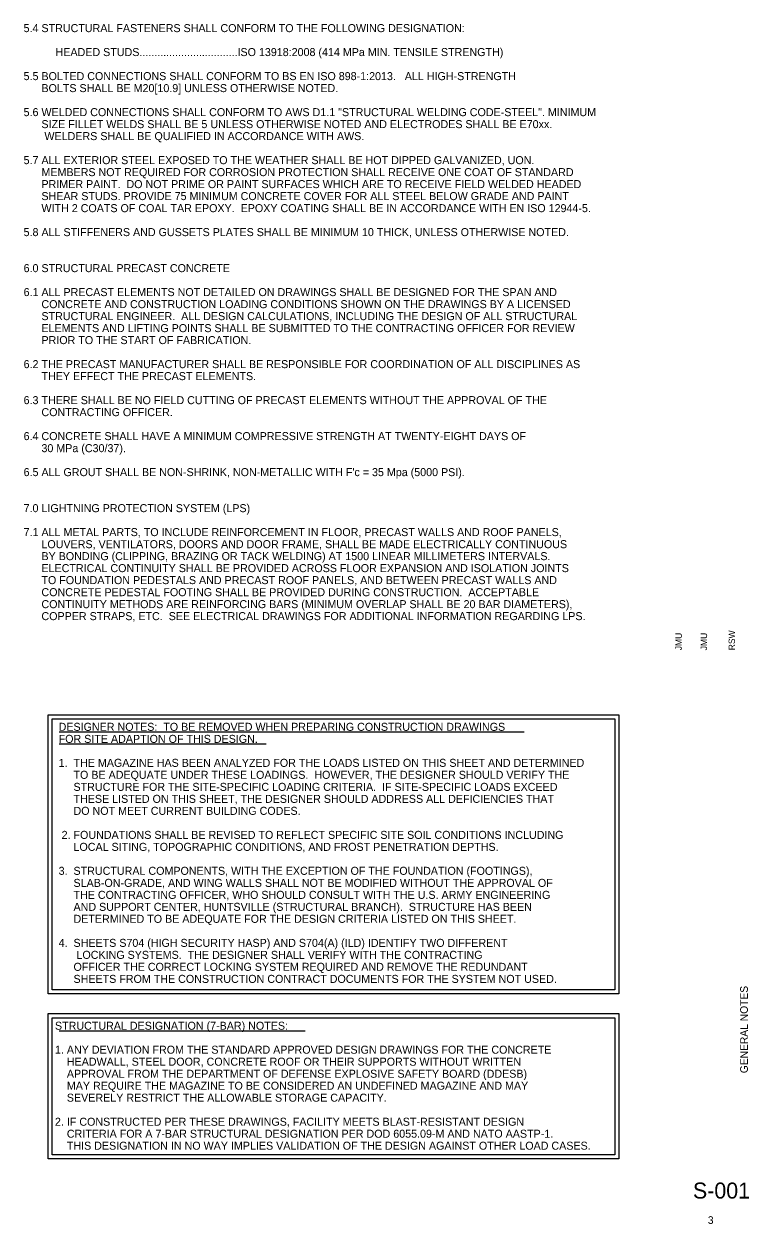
# Model space of a CAD drawing. Extents: x 0.17 to 2.69, y 0.11 to 1.7.
# Drawn here: x 1.747 to 2.69, y 0.138 to 1.7 of the extents above; entities that cross this region are included whole.
import ezdxf

# ---------------------------------------------------------------- set-up
doc = ezdxf.new("R2010")
doc.units = 0
doc.layers.add('G-ANNO-TEXT', color=7, linetype='Continuous')
doc.layers.add('G-ANNO-TTLB', color=7, linetype='Continuous')

msp = doc.modelspace()

# ---------------------------------------------------------------- linework, layer by layer
at = {"layer": 'G-ANNO-TEXT'}
for p, q in [((1.7925, 0.7787), (2.3978, 0.7787)), ((1.7925, 0.7631), (2.062, 0.7631)), ((1.7925, 0.3896), (2.1125, 0.3896))]:
    msp.add_line(p, q, dxfattribs=at)
for points in [[(1.7783, 0.8011), (2.5212, 0.8011), (2.5212, 0.4379), (1.7783, 0.4379)], [(1.7835, 0.7959), (2.516, 0.7959), (2.516, 0.4431), (1.7835, 0.4431)], [(1.7783, 0.412), (2.5212, 0.412), (2.5212, 0.2228), (1.7783, 0.2228)], [(1.7835, 0.4067), (2.516, 0.4067), (2.516, 0.228), (1.7835, 0.228)]]:
    msp.add_lwpolyline(points, close=True, dxfattribs=at)

# ---------------------------------------------------------------- texts
for s, p in [('5.4 STRUCTURAL FASTENERS SHALL CONFORM TO THE FOLLOWING DESIGNATION:', (1.7462, 1.6899)), ('HEADED STUDS.................................ISO 13918:2008 (414 MPa MIN. TENSILE STRENGTH)', (1.7878, 1.6587)), ('5.5 BOLTED CONNECTIONS SHALL CONFORM TO BS EN ISO 898-1:2013.   ALL HIGH-STRENGTH', (1.7462, 1.6274)), ('      BOLTS SHALL BE M20[10.9] UNLESS OTHERWISE NOTED.', (1.7462, 1.6118)), ('5.6 WELDED CONNECTIONS SHALL CONFORM TO AWS D1.1 "STRUCTURAL WELDING CODE-STEEL". MINIMUM', (1.7462, 1.5805)), ('      SIZE FILLET WELDS SHALL BE 5 UNLESS OTHERWISE NOTED AND ELECTRODES SHALL BE E70xx. ', (1.7462, 1.5649)), ('       WELDERS SHALL BE QUALIFIED IN ACCORDANCE WITH AWS.', (1.7462, 1.5493)), ('5.7 ALL EXTERIOR STEEL EXPOSED TO THE WEATHER SHALL BE HOT DIPPED GALVANIZED, UON. ', (1.7462, 1.518)), ('      MEMBERS NOT REQUIRED FOR CORROSION PROTECTION SHALL RECEIVE ONE COAT OF STANDARD ', (1.7462, 1.5024)), ('      PRIMER PAINT.  DO NOT PRIME OR PAINT SURFACES WHICH ARE TO RECEIVE FIELD WELDED HEADED ', (1.7462, 1.4868)), ('      SHEAR STUDS. PROVIDE 75 MINIMUM CONCRETE COVER FOR ALL STEEL BELOW GRADE AND PAINT ', (1.7462, 1.4712)), ('      WITH 2 COATS OF COAL TAR EPOXY.  EPOXY COATING SHALL BE IN ACCORDANCE WITH EN ISO 12944-5.   ', (1.7462, 1.4555)), ('5.8 ALL STIFFENERS AND GUSSETS PLATES SHALL BE MINIMUM 10 THICK, UNLESS OTHERWISE NOTED. ', (1.7462, 1.4243)), ('6.0 STRUCTURAL PRECAST CONCRETE', (1.7462, 1.3774)), ('6.1 ALL PRECAST ELEMENTS NOT DETAILED ON DRAWINGS SHALL BE DESIGNED FOR THE SPAN AND', (1.7462, 1.3462)), ('      CONCRETE AND CONSTRUCTION LOADING CONDITIONS SHOWN ON THE DRAWINGS BY A LICENSED', (1.7462, 1.3305)), ('      STRUCTURAL ENGINEER.  ALL DESIGN CALCULATIONS, INCLUDING THE DESIGN OF ALL STRUCTURAL', (1.7462, 1.3149)), ('      ELEMENTS AND LIFTING POINTS SHALL BE SUBMITTED TO THE CONTRACTING OFFICER FOR REVIEW', (1.7462, 1.2993)), ('      PRIOR TO THE START OF FABRICATION.', (1.7462, 1.2837)), ('6.2 THE PRECAST MANUFACTURER SHALL BE RESPONSIBLE FOR COORDINATION OF ALL DISCIPLINES AS', (1.7462, 1.2524)), ('      THEY EFFECT THE PRECAST ELEMENTS.', (1.7462, 1.2368)), ('6.3 THERE SHALL BE NO FIELD CUTTING OF PRECAST ELEMENTS WITHOUT THE APPROVAL OF THE', (1.7462, 1.2055)), ('      CONTRACTING OFFICER.', (1.7462, 1.1899)), ('6.4 CONCRETE SHALL HAVE A MINIMUM COMPRESSIVE STRENGTH AT TWENTY-EIGHT DAYS OF', (1.7462, 1.1587)), ('      30 MPa (C30/37).', (1.7462, 1.143)), ("6.5 ALL GROUT SHALL BE NON-SHRINK, NON-METALLIC WITH F'c = 35 Mpa (5000 PSI).", (1.7462, 1.1118)), ('7.0 LIGHTNING PROTECTION SYSTEM (LPS)', (1.7462, 1.0649)), ('7.1 ALL METAL PARTS, TO INCLUDE REINFORCEMENT IN FLOOR, PRECAST WALLS AND ROOF PANELS,', (1.7462, 1.0337)), ('      LOUVERS, VENTILATORS, DOORS AND DOOR FRAME, SHALL BE MADE ELECTRICALLY CONTINUOUS', (1.7462, 1.018)), ('      BY BONDING (CLIPPING, BRAZING OR TACK WELDING) AT 1500 LINEAR MILLIMETERS INTERVALS.  ', (1.7462, 1.0024)), ('      ELECTRICAL CONTINUITY SHALL BE PROVIDED ACROSS FLOOR EXPANSION AND ISOLATION JOINTS', (1.7462, 0.9868)), ('      TO FOUNDATION PEDESTALS AND PRECAST ROOF PANELS, AND BETWEEN PRECAST WALLS AND', (1.7462, 0.9712)), ('      CONCRETE PEDESTAL FOOTING SHALL BE PROVIDED DURING CONSTRUCTION.  ACCEPTABLE', (1.7462, 0.9555)), ('      CONTINUITY METHODS ARE REINFORCING BARS (MINIMUM OVERLAP SHALL BE 20 BAR DIAMETERS),', (1.7462, 0.9399)), ('      COPPER STRAPS, ETC.  SEE ELECTRICAL DRAWINGS FOR ADDITIONAL INFORMATION REGARDING LPS.', (1.7462, 0.9243)), ('DESIGNER NOTES:  TO BE REMOVED WHEN PREPARING CONSTRUCTION DRAWINGS ', (1.7918, 0.7802)), ('FOR SITE ADAPTION OF THIS DESIGN.', (1.7918, 0.7645)), ('1.  THE MAGAZINE HAS BEEN ANALYZED FOR THE LOADS LISTED ON THIS SHEET AND DETERMINED', (1.7918, 0.7333)), ('     TO BE ADEQUATE UNDER THESE LOADINGS.  HOWEVER, THE DESIGNER SHOULD VERIFY THE ', (1.7918, 0.7177)), ('     STRUCTURE FOR THE SITE-SPECIFIC LOADING CRITERIA.  IF SITE-SPECIFIC LOADS EXCEED ', (1.7918, 0.702)), ('     THESE LISTED ON THIS SHEET, THE DESIGNER SHOULD ADDRESS ALL DEFICIENCIES THAT', (1.7918, 0.6864)), ('     DO NOT MEET CURRENT BUILDING CODES. ', (1.7918, 0.6708)), (' 2. FOUNDATIONS SHALL BE REVISED TO REFLECT SPECIFIC SITE SOIL CONDITIONS INCLUDING', (1.7918, 0.6395)), ('     LOCAL SITING, TOPOGRAPHIC CONDITIONS, AND FROST PENETRATION DEPTHS.', (1.7918, 0.6239)), ('3.  STRUCTURAL COMPONENTS, WITH THE EXCEPTION OF THE FOUNDATION (FOOTINGS),', (1.7918, 0.5927)), ('     SLAB-ON-GRADE, AND WING WALLS SHALL NOT BE MODIFIED WITHOUT THE APPROVAL OF', (1.7918, 0.577)), ('     THE CONTRACTING OFFICER, WHO SHOULD CONSULT WITH THE U.S. ARMY ENGINEERING', (1.7918, 0.5614)), ('     AND SUPPORT CENTER, HUNTSVILLE (STRUCTURAL BRANCH).  STRUCTURE HAS BEEN', (1.7918, 0.5458)), ('     DETERMINED TO BE ADEQUATE FOR THE DESIGN CRITERIA LISTED ON THIS SHEET.    ', (1.7918, 0.5302)), ('4.  SHEETS S704 (HIGH SECURITY HASP) AND S704(A) (ILD) IDENTIFY TWO DIFFERENT', (1.7918, 0.4989)), ('      LOCKING SYSTEMS.  THE DESIGNER SHALL VERIFY WITH THE CONTRACTING', (1.7918, 0.4833)), ('     OFFICER THE CORRECT LOCKING SYSTEM REQUIRED AND REMOVE THE REDUNDANT', (1.7918, 0.4677)), ('     SHEETS FROM THE CONSTRUCTION CONTRACT DOCUMENTS FOR THE SYSTEM NOT USED.', (1.7918, 0.452)), ('STRUCTURAL DESIGNATION (7-BAR) NOTES:', (1.787, 0.391)), ('1. ANY DEVIATION FROM THE STANDARD APPROVED DESIGN DRAWINGS FOR THE CONCRETE', (1.787, 0.3598)), ('    HEADWALL, STEEL DOOR, CONCRETE ROOF OR THEIR SUPPORTS WITHOUT WRITTEN ', (1.787, 0.3442)), ('    APPROVAL FROM THE DEPARTMENT OF DEFENSE EXPLOSIVE SAFETY BOARD (DDESB)', (1.787, 0.3285)), ('    MAY REQUIRE THE MAGAZINE TO BE CONSIDERED AN UNDEFINED MAGAZINE AND MAY ', (1.787, 0.3129)), ('    SEVERELY RESTRICT THE ALLOWABLE STORAGE CAPACITY.', (1.787, 0.2973)), ('2. IF CONSTRUCTED PER THESE DRAWINGS, FACILITY MEETS BLAST-RESISTANT DESIGN', (1.787, 0.266)), ('    CRITERIA FOR A 7-BAR STRUCTURAL DESIGNATION PER DOD 6055.09-M AND NATO AASTP-1.', (1.787, 0.2504)), ('    THIS DESIGNATION IN NO WAY IMPLIES VALIDATION OF THE DESIGN AGAINST OTHER LOAD CASES.', (1.787, 0.2348))]:
    msp.add_text(s, height=0.010417, dxfattribs=at).set_placement(p)
at = {"layer": 'G-ANNO-TTLB'}
for s, height, p in [('JMU', 0.00833, (2.603, 0.885)), ('JMU', 0.00833, (2.6359, 0.885)), ('RSW', 0.00833, (2.6722, 0.885)), ('GENERAL NOTES', 0.01, (2.689, 0.3344))]:
    msp.add_text(s, height=height, rotation=90, dxfattribs=at).set_placement(p)
for s, height, p in [('S-001', 0.02083, (2.6175, 0.1712)), ('3', 0.01, (2.6369, 0.1382))]:
    msp.add_text(s, height=height, dxfattribs=at).set_placement(p)

doc.saveas('drawing.dxf')
